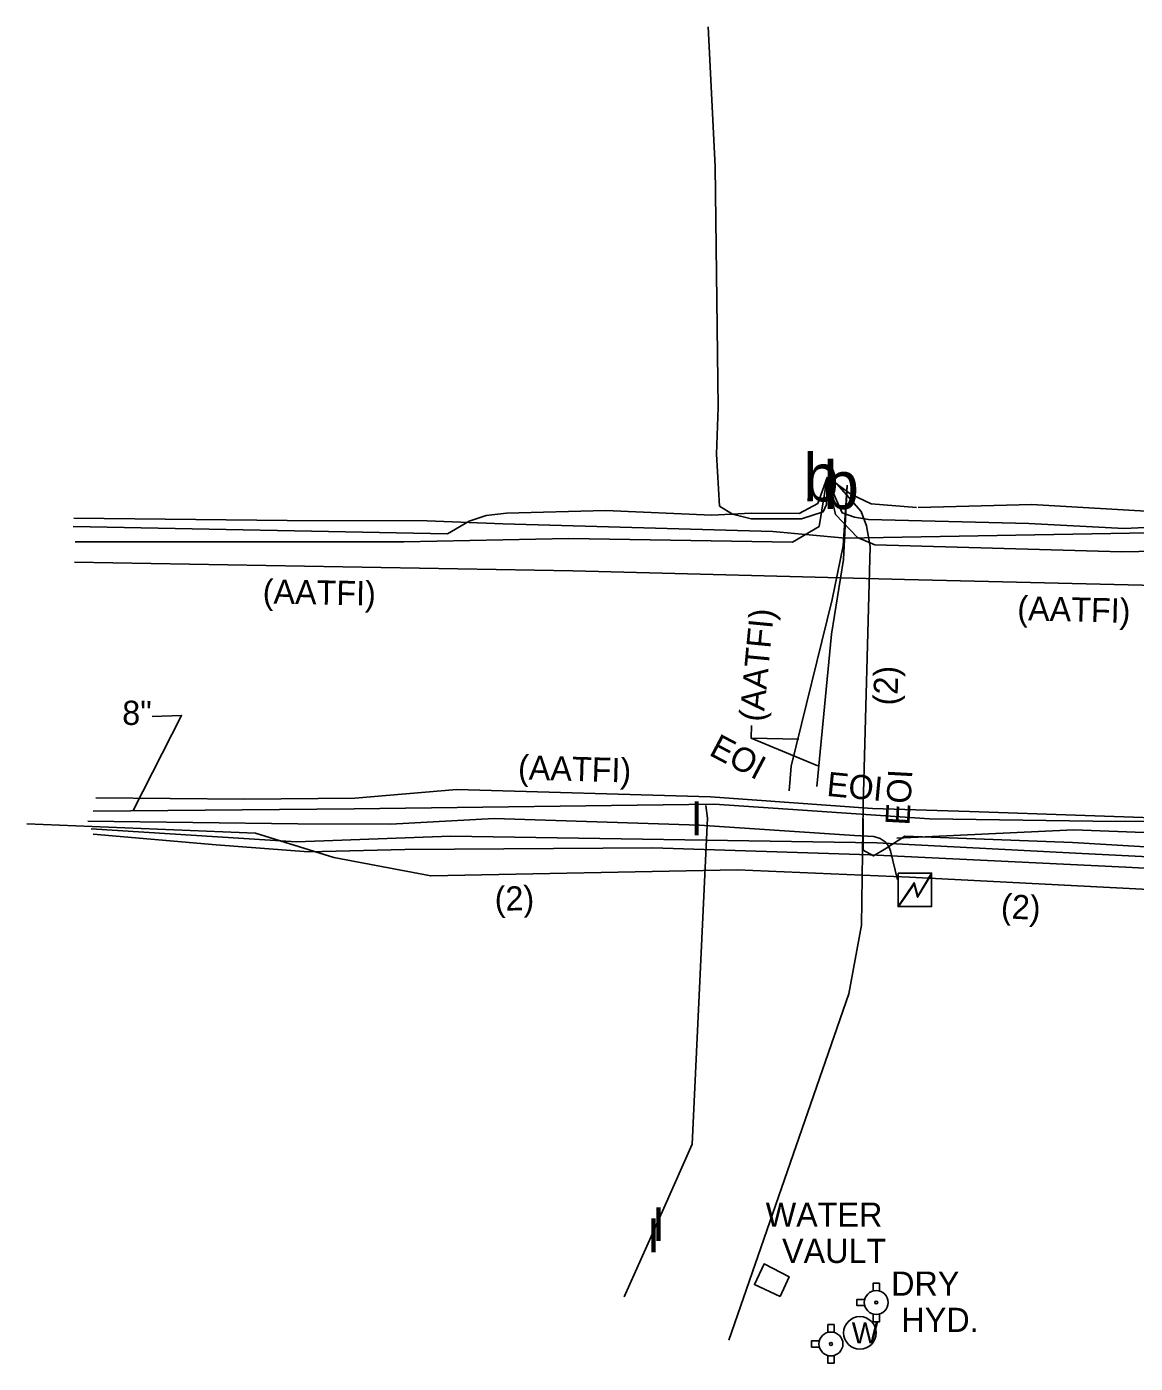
# Model space of a CAD drawing. Extents: x 1975707 to 1978340, y 778386 to 782872.
# Drawn here: x 1976004 to 1976187.5, y 779425.3 to 779646.5 of the extents above; entities that cross this region are included whole.
import ezdxf

# ---------------------------------------------------------------- set-up
doc = ezdxf.new("R2010")
doc.units = 0
for name, color, linetype in [('Exist Utilities Power Transformer CELL', 7, 'Continuous'), ('Exist Utilities Power UG Cable', 7, 'Continuous'), ('Exist Utilities Power UG Cable SUE', 7, 'Continuous'), ('Exist Utilities Power UG Cable Text', 7, 'Continuous'), ('Exist Utilities Telephone Pedestal CELL', 7, 'Continuous'), ('Exist Utilities Telephone UG Cable', 7, 'Continuous'), ('Exist Utilities Telephone UG Cable SUE', 7, 'Continuous'), ('Exist Utilities Telephone UG Cable SUE Text', 7, 'Continuous'), ('Exist Utilities Telephone UG FO', 7, 'Continuous'), ('Exist Utilities TV UG Cable SUE', 7, 'Continuous'), ('Exist Utilities TV UG Cable SUE Leader', 7, 'Continuous'), ('Exist Utilities TV UG Cable SUE Text', 7, 'Continuous'), ('Exist Utilities Water Fire Hydrant CELL', 7, 'Continuous'), ('Exist Utilities Water Manhole CELL', 7, 'Continuous'), ('Exist Utilities Water UG Line', 7, 'Continuous'), ('Exist Utilities Water UG Line SUE', 7, 'Continuous'), ('Exist Utilities Water UG Line SUE Leader', 7, 'Continuous'), ('Exist Utilities Water UG Line SUE Text', 7, 'Continuous'), ('Exist Utilities Water Valve CELL', 7, 'Continuous')]:
    doc.layers.add(name, color=color, linetype=linetype)

# ---------------------------------------------------------------- blocks, each defined once
blk = doc.blocks.new('EXIST UTILITIES WATER MANHOLE')
at = {"layer": 'Exist Utilities Water Manhole CELL'}
blk.add_line((0, 0), (0, 0), dxfattribs=at)
blk.add_circle((0, 0.0001), 0.0539, dxfattribs=at)
blk.add_text('W', height=0.07, dxfattribs=at).set_placement((-0.027, -0.035))

msp = doc.modelspace()

# ---------------------------------------------------------------- linework, layer by layer
at = {"layer": 'Exist Utilities Power Transformer CELL'}
msp.add_line((1976151.12, 779503.77), (1976151.12, 779503.77), dxfattribs=at)
msp.add_lwpolyline([(1976148.28, 779506.38), (1976153.83, 779506.38), (1976153.83, 779500.83), (1976148.28, 779500.83)], close=True, dxfattribs=at)
for points in [[(1976148.28, 779500.83), (1976150.92, 779504.77), (1976151.55, 779502.56), (1976153.83, 779506.38)], [(1976148.35, 779500.83), (1976150.92, 779504.56), (1976151.51, 779502.38), (1976153.83, 779506.23)]]:
    msp.add_lwpolyline(points, dxfattribs=at)
at = {"layer": 'Exist Utilities Power UG Cable'}
for points in [[(1976014.13, 779514.97), (1976048.89, 779514.51), (1976064.23, 779514.46), (1976081.44, 779515.43), (1976115.39, 779514.33), (1976141.05, 779512.61)], [(1976141.05, 779512.61), (1976144.29, 779512.44), (1976145.29, 779512.13), (1976146.13, 779511.57), (1976146.67, 779510.91), (1976147.03, 779510.08), (1976148.17, 779505.25)]]:
    msp.add_lwpolyline(points, dxfattribs=at)
at = {"layer": 'Exist Utilities Power UG Cable SUE'}
for points in [[(1976011.84, 779565.14), (1976047.15, 779564.73), (1976070.33, 779564.69), (1976082.87, 779564.16), (1976127.53, 779562.89), (1976139.59, 779561.79), (1976192.91, 779562.77)], [(1976148.1, 779512.14), (1976177.37, 779513.52), (1976220.97, 779511.91), (1976254.41, 779511.32), (1976292.14, 779509.39), (1976324.09, 779507.51), (1976333.03, 779505.98), (1976334, 779504.85), (1976334.09, 779503.67), (1976330.2, 779498.14), (1976321.55, 779487.07)]]:
    msp.add_lwpolyline(points, dxfattribs=at)
at = {"layer": 'Exist Utilities Telephone UG Cable'}
msp.add_lwpolyline([(1976012.08, 779561.2), (1976066.45, 779561.19), (1976093.77, 779561.74), (1976130.78, 779561.13), (1976135.21, 779563.77), (1976136.54, 779571.86)], dxfattribs=at)
at = {"layer": 'Exist Utilities Telephone UG Cable SUE'}
for points in [[(1976011.72, 779563.75), (1976073.72, 779562.54), (1976077.3, 779564.64), (1976080.11, 779565.59), (1976083.47, 779565.95), (1976099.87, 779566.41), (1976117.44, 779565.64), (1976123.98, 779565.93), (1976131.92, 779565.89), (1976134.98, 779567.57), (1976136.54, 779571.86), (1976136.43, 779567.39), (1976135.86, 779566.15), (1976132.3, 779564.99), (1976123.97, 779565.02), (1976120.89, 779565.8), (1976118.72, 779567.13), (1976118.21, 779575.71), (1976118.5, 779583.44), (1976118, 779623.35), (1976116.85, 779646.46)], [(1976143.39, 779564.9), (1976169.9, 779564.25), (1976185.73, 779563.43), (1976199.63, 779564.08), (1976206.99, 779568.29), (1976212, 779569.78), (1976253.03, 779569.65), (1976277.85, 779566.91), (1976281.4, 779566.57), (1976283.96, 779568.31), (1976288.21, 779572), (1976301.36, 779587.94), (1976312, 779601.16), (1976326.57, 779617.82), (1976338.41, 779630.81)], [(1976151.61, 779566.87), (1976170.43, 779567.37), (1976198.81, 779565.74), (1976212.02, 779564.25), (1976252.92, 779563.76), (1976273.66, 779563.11), (1976315.77, 779562.27), (1976360.75, 779561.66), (1976373.3, 779562.06), (1976382.96, 779563.58), (1976387.68, 779565.55), (1976393.78, 779569.39), (1976400.86, 779575.94), (1976406.68, 779579.9), (1976416.36, 779583), (1976425.95, 779584.03), (1976432.63, 779585.51), (1976437.83, 779585.67), (1976442.68, 779583.08)], [(1976120.26, 779429.08), (1976140.13, 779486.38), (1976142.21, 779497.78), (1976142.53, 779517.65), (1976143.66, 779560.43), (1976143.07, 779563.88), (1976142.15, 779566.23), (1976138.15, 779570.78), (1976136.66, 779571.86), (1976140.47, 779569.12), (1976143.8, 779567.51), (1976151.32, 779566.88)], [(1976143.38, 779564.89), (1976141.08, 779565.31), (1976139.01, 779565.98), (1976137.85, 779568.58), (1976136.53, 779571.81), (1976137.9, 779565.74), (1976141.56, 779561.9), (1976144.46, 779560.71), (1976185.3, 779559.54), (1976210.59, 779560.07)], [(1976130.25, 779519.98), (1976130.6, 779524.1), (1976137.38, 779551.68), (1976139.21, 779560.57), (1976139.88, 779570.6)], [(1976014.7, 779513.69), (1976048.67, 779511.54), (1976074.19, 779512.49), (1976144.76, 779511.4), (1976177.66, 779509.7), (1976220.53, 779507.54), (1976271.51, 779504.64), (1976318.13, 779506.19), (1976323.68, 779508.03), (1976335.23, 779510.8), (1976339.43, 779510.45), (1976344.41, 779508.25), (1976347.38, 779507.19)], [(1976142.5, 779515.42), (1976142.5, 779510.18), (1976144.22, 779509.21), (1976146.26, 779510.44), (1976149.4, 779512.47), (1976177.15, 779511.42), (1976227.22, 779508.48), (1976251.09, 779506.08), (1976284.16, 779505.86), (1976309.78, 779507.06), (1976330.74, 779508.41), (1976338.83, 779510.04), (1976341.67, 779509.12), (1976345.34, 779505.9), (1976346.18, 779504.07), (1976347.73, 779507.15)]]:
    msp.add_lwpolyline(points, dxfattribs=at)
at = {"layer": 'Exist Utilities Telephone UG FO'}
msp.add_lwpolyline([(1976015.01, 779512.83), (1976035.38, 779511.03), (1976050.7, 779509.91), (1976066.61, 779510.29), (1976107.65, 779510.54), (1976143.63, 779509.4), (1976185.96, 779507.34), (1976234.35, 779504.85), (1976273, 779502.65), (1976313.24, 779503.73), (1976341.25, 779504.71), (1976349.11, 779505.81), (1976370.95, 779532.7), (1976386.68, 779553.36), (1976398.9, 779559.48), (1976407.5, 779563.26), (1976418.01, 779571.76), (1976428.54, 779582.88), (1976461.96, 779617.97)], dxfattribs=at)
at = {"layer": 'Exist Utilities TV UG Cable SUE'}
for points in [[(1976011.96, 779557.82), (1976094.42, 779556.43), (1976149.35, 779554.99), (1976197.94, 779553.82), (1976272.15, 779552.21), (1976344.84, 779550.69), (1976386.68, 779550.37), (1976389.72, 779558.04), (1976397.78, 779565.54), (1976414.26, 779581.87), (1976418.58, 779588.17), (1976417.95, 779589.63)], [(1976134.85, 779520.69), (1976137.27, 779545.9), (1976139.23, 779558.26), (1976139.88, 779570.6)], [(1976015.5, 779518.83), (1976040.11, 779518.59), (1976058.36, 779518.79), (1976075.21, 779520.19), (1976117.23, 779518.98), (1976144.05, 779517.05), (1976160.11, 779516.59), (1976198.39, 779515.23)], [(1976004.04, 779514.53), (1976041.9, 779512.97), (1976054.86, 779508.97), (1976070.93, 779505.92), (1976121.65, 779506.93), (1976150.18, 779505.72), (1976215.46, 779502.34), (1976246.11, 779500.79), (1976284.39, 779495.16), (1976289.72, 779490.62), (1976290.33, 779480.53), (1976300.2, 779471.55), (1976308.47, 779462.38)]]:
    msp.add_lwpolyline(points, dxfattribs=at)
at = {"layer": 'Exist Utilities TV UG Cable SUE Leader'}
for points in [[(1976134.99, 779524.13), (1976123.94, 779528.72), (1976124.03, 779530.81)], [(1976131.86, 779528.53), (1976123.94, 779528.72)]]:
    msp.add_lwpolyline(points, dxfattribs=at)
at = {"layer": 'Exist Utilities Water Fire Hydrant CELL'}
for p, q in [((1976144.67, 779435.31), (1976144.67, 779435.31)), ((1976137.17, 779428.45), (1976137.17, 779428.45))]:
    msp.add_line(p, q, dxfattribs=at)
for points in [[(1976128.76, 779436.28), (1976130.26, 779439.54), (1976126.1, 779441.69), (1976124.49, 779438.28), (1976128.76, 779436.28)], [(1976144.15, 779437.22), (1976144.15, 779438.51), (1976145.18, 779438.51), (1976145.18, 779437.2)], [(1976142.75, 779435.82), (1976141.47, 779435.82), (1976141.47, 779434.8), (1976142.75, 779434.8)], [(1976144.15, 779433.4), (1976144.15, 779432.11), (1976145.18, 779432.11), (1976145.18, 779433.42)], [(1976136.66, 779430.37), (1976136.66, 779431.66), (1976137.68, 779431.66), (1976137.68, 779430.34)], [(1976135.26, 779428.97), (1976133.97, 779428.97), (1976133.97, 779427.94), (1976135.26, 779427.94)], [(1976136.66, 779426.54), (1976136.66, 779425.26), (1976137.68, 779425.26), (1976137.68, 779426.57)]]:
    msp.add_lwpolyline(points, dxfattribs=at)
for centre, radius in [((1976144.67, 779435.31), 1.98), ((1976144.67, 779435.31), 0.243), ((1976137.17, 779428.45), 1.98), ((1976137.17, 779428.45), 0.243)]:
    msp.add_circle(centre, radius, dxfattribs=at)
at = {"layer": 'Exist Utilities Water UG Line'}
msp.add_lwpolyline([(1976015.05, 779516.64), (1976058.22, 779516.99)], dxfattribs=at)
at = {"layer": 'Exist Utilities Water UG Line SUE'}
for points in [[(1976058.22, 779516.99), (1976117.87, 779517.77), (1976153.51, 779515.35), (1976180.52, 779514.99), (1976200, 779514.87), (1976215.3, 779515.93), (1976250.71, 779516.67), (1976278.55, 779516.25), (1976310.54, 779515.32), (1976342.47, 779513.59), (1976351.24, 779512.43), (1976362.38, 779514.18), (1976374.05, 779516.38), (1976407.48, 779494.27)], [(1976102.96, 779436.23), (1976109.52, 779450.9), (1976114.17, 779461.51), (1976116.71, 779515.45), (1976116.48, 779517.55)]]:
    msp.add_lwpolyline(points, dxfattribs=at)
at = {"layer": 'Exist Utilities Water UG Line SUE Leader'}
msp.add_lwpolyline([(1976021.65, 779516.75), (1976029.67, 779532.48), (1976024.82, 779532.3)], dxfattribs=at)

# ---------------------------------------------------------------- block references
at = {"layer": 'Exist Utilities Water Fire Hydrant CELL', "xscale": 50, "yscale": 50}
msp.add_blockref('EXIST UTILITIES WATER MANHOLE', (1976141.96, 779430.28), dxfattribs=at)

# ---------------------------------------------------------------- texts
at = {"layer": 'Exist Utilities Power UG Cable Text'}
msp.add_text('EOI', height=4, rotation=86.8949, dxfattribs=at).set_placement((1976150.16, 779514.22))
at = {"layer": 'Exist Utilities Telephone Pedestal CELL'}
for p in [(1976132.58, 779567.9), (1976135.92, 779566.64)]:
    msp.add_text('b', height=7.92, dxfattribs=at).set_placement(p)
at = {"layer": 'Exist Utilities Telephone UG Cable SUE Text'}
for s, rotation, p in [('(2)', 88.4955, (1976148.17, 779534.09)), ('EOI', 332.2042, (1976116.81, 779526.01))]:
    msp.add_text(s, height=4, rotation=rotation, dxfattribs=at).set_placement(p)
at = {"layer": 'Exist Utilities TV UG Cable SUE Text'}
for s, rotation, p in [('(AATFI)', 359.0312, (1976043.08, 779550.99)), ('(AATFI)', 358.614, (1976167.99, 779548.24)), ('(AATFI)', 84.5099, (1976125.97, 779531.34)), ('(AATFI)', 358.348, (1976085.33, 779521.9)), ('EOI', 354.5099, (1976136.36, 779519.17)), ('(2)', 1.1415, (1976081.54, 779500.13)), ('(2)', 357.0326, (1976165.24, 779498.94))]:
    msp.add_text(s, height=4, rotation=rotation, dxfattribs=at).set_placement(p)
at = {"layer": 'Exist Utilities Water Fire Hydrant CELL'}
for s, p in [('WATER ', (1976126.37, 779447.85)), ('VAULT', (1976129.08, 779441.85)), ('DRY ', (1976147.14, 779436.44)), ('HYD.', (1976148.84, 779430.44))]:
    msp.add_text(s, height=4, rotation=0, dxfattribs=at).set_placement(p)
at = {"layer": 'Exist Utilities Water UG Line SUE Text'}
msp.add_text('8"', height=4, rotation=359.7283, dxfattribs=at).set_placement((1976019.84, 779530.91))
at = {"layer": 'Exist Utilities Water Valve CELL'}
for p in [(1976113.89, 779512.64), (1976107.57, 779445.47), (1976106.76, 779443.64)]:
    msp.add_text('I', height=5.62, dxfattribs=at).set_placement(p)

doc.saveas('drawing.dxf')
